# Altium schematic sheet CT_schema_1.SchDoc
size 736 x 683 mm
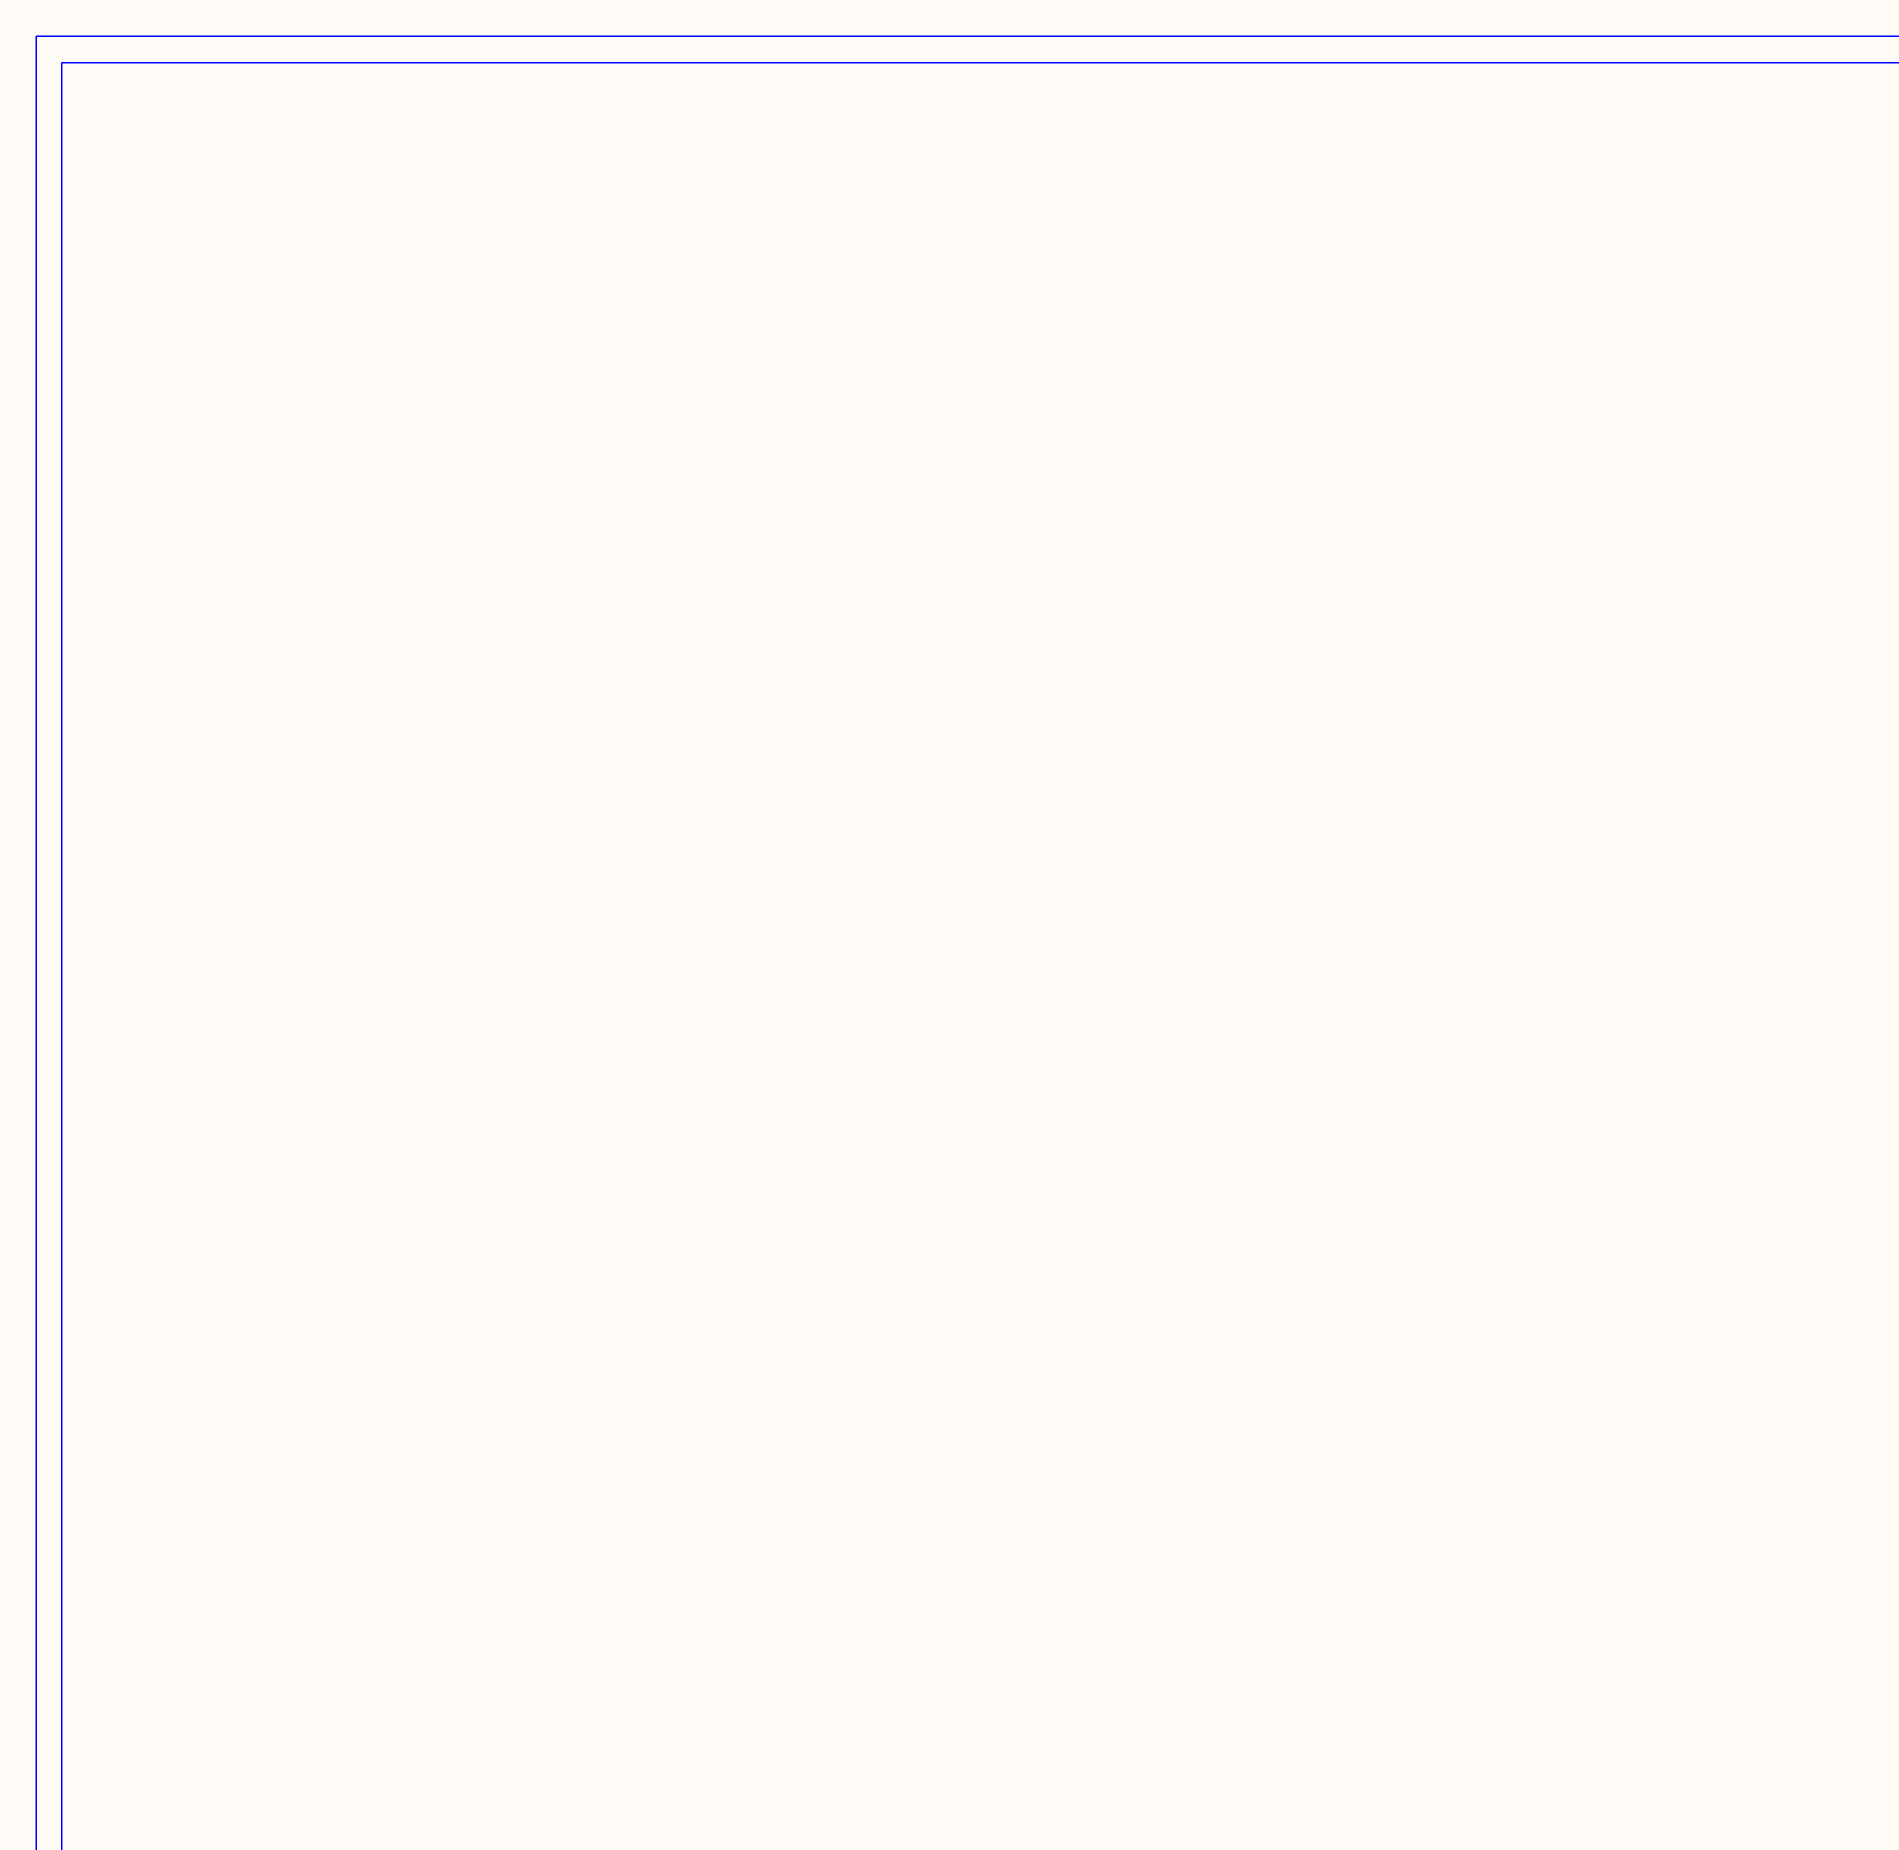
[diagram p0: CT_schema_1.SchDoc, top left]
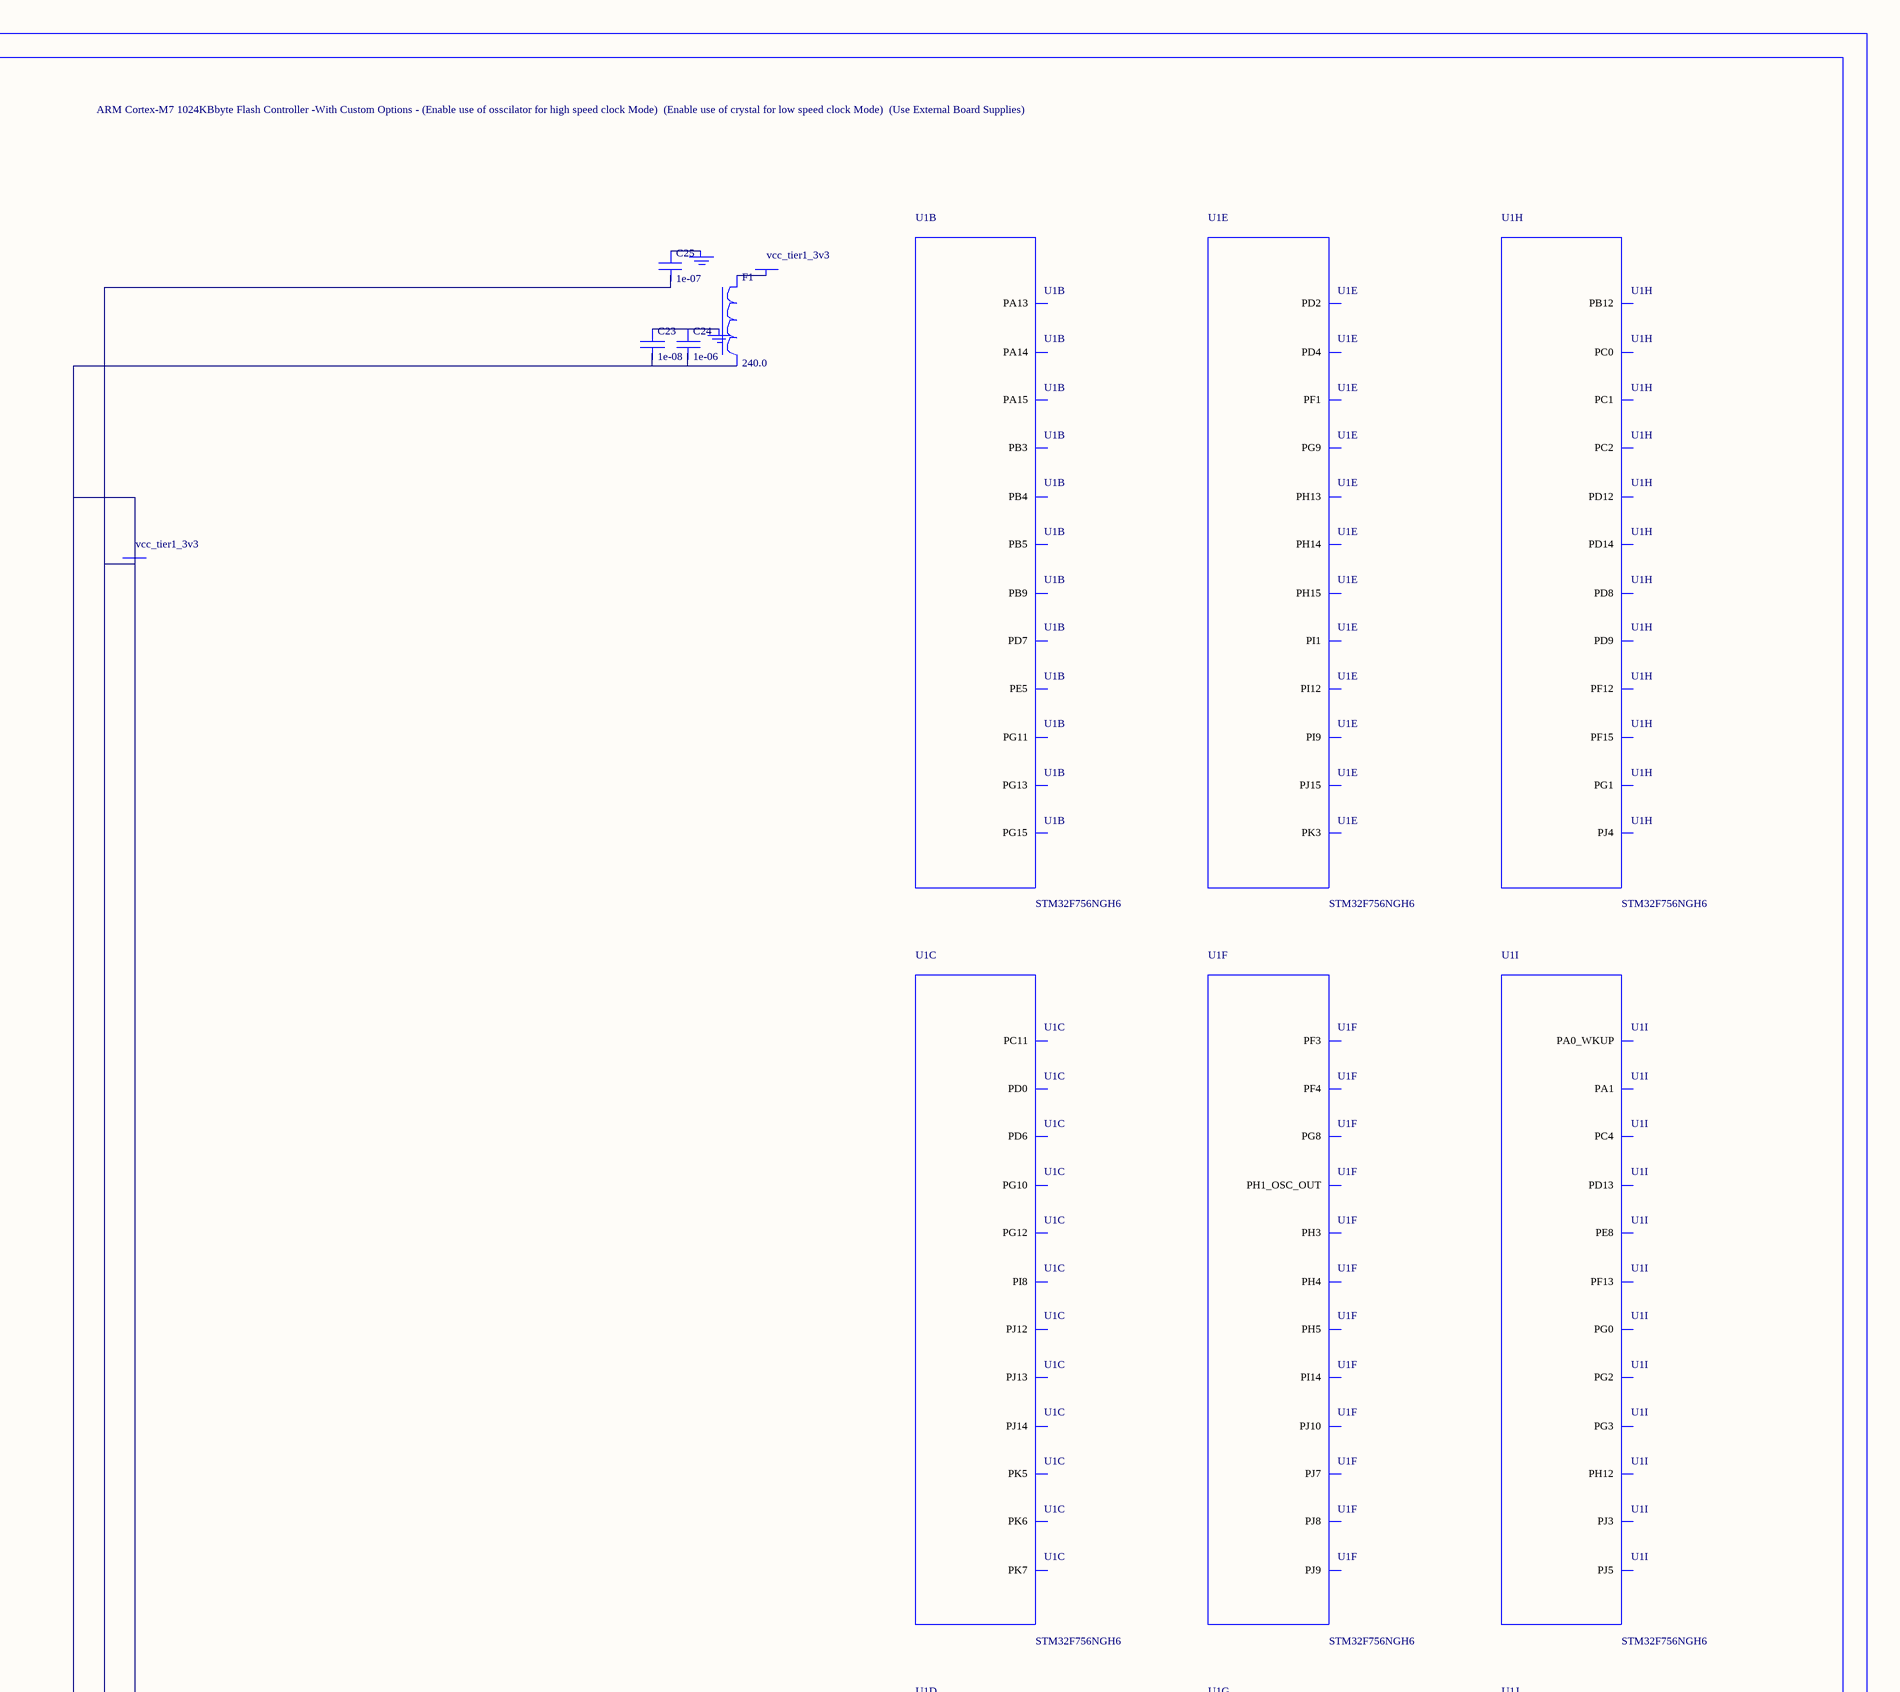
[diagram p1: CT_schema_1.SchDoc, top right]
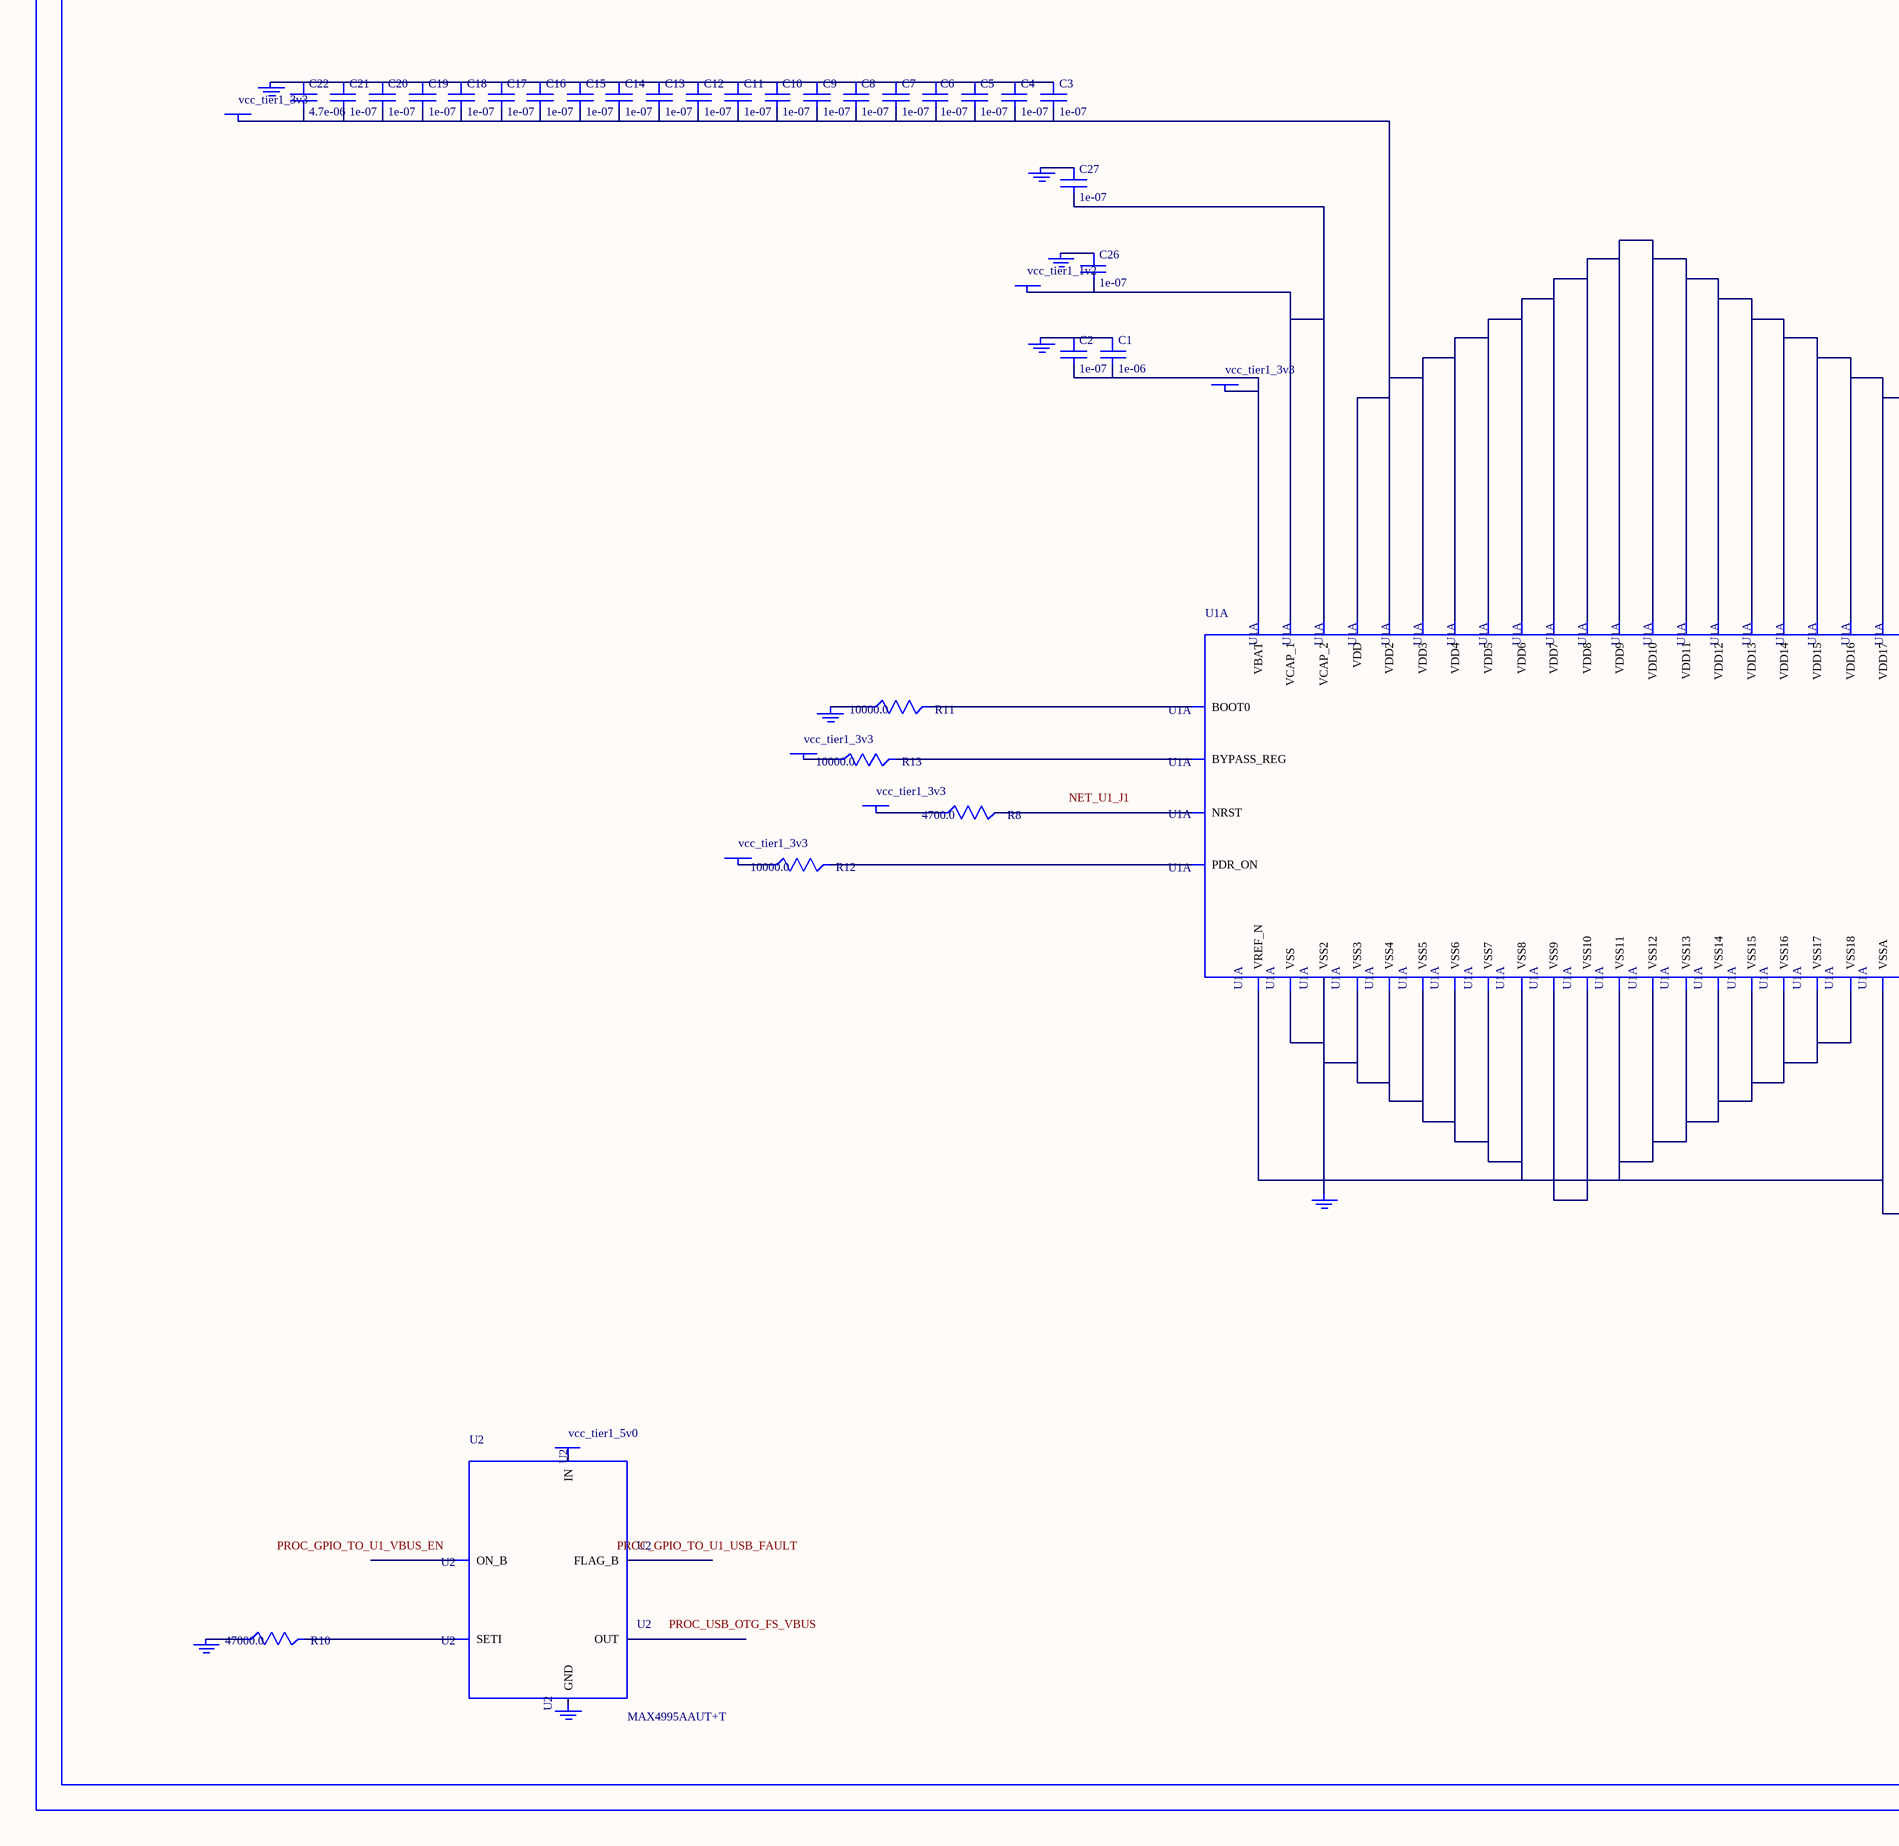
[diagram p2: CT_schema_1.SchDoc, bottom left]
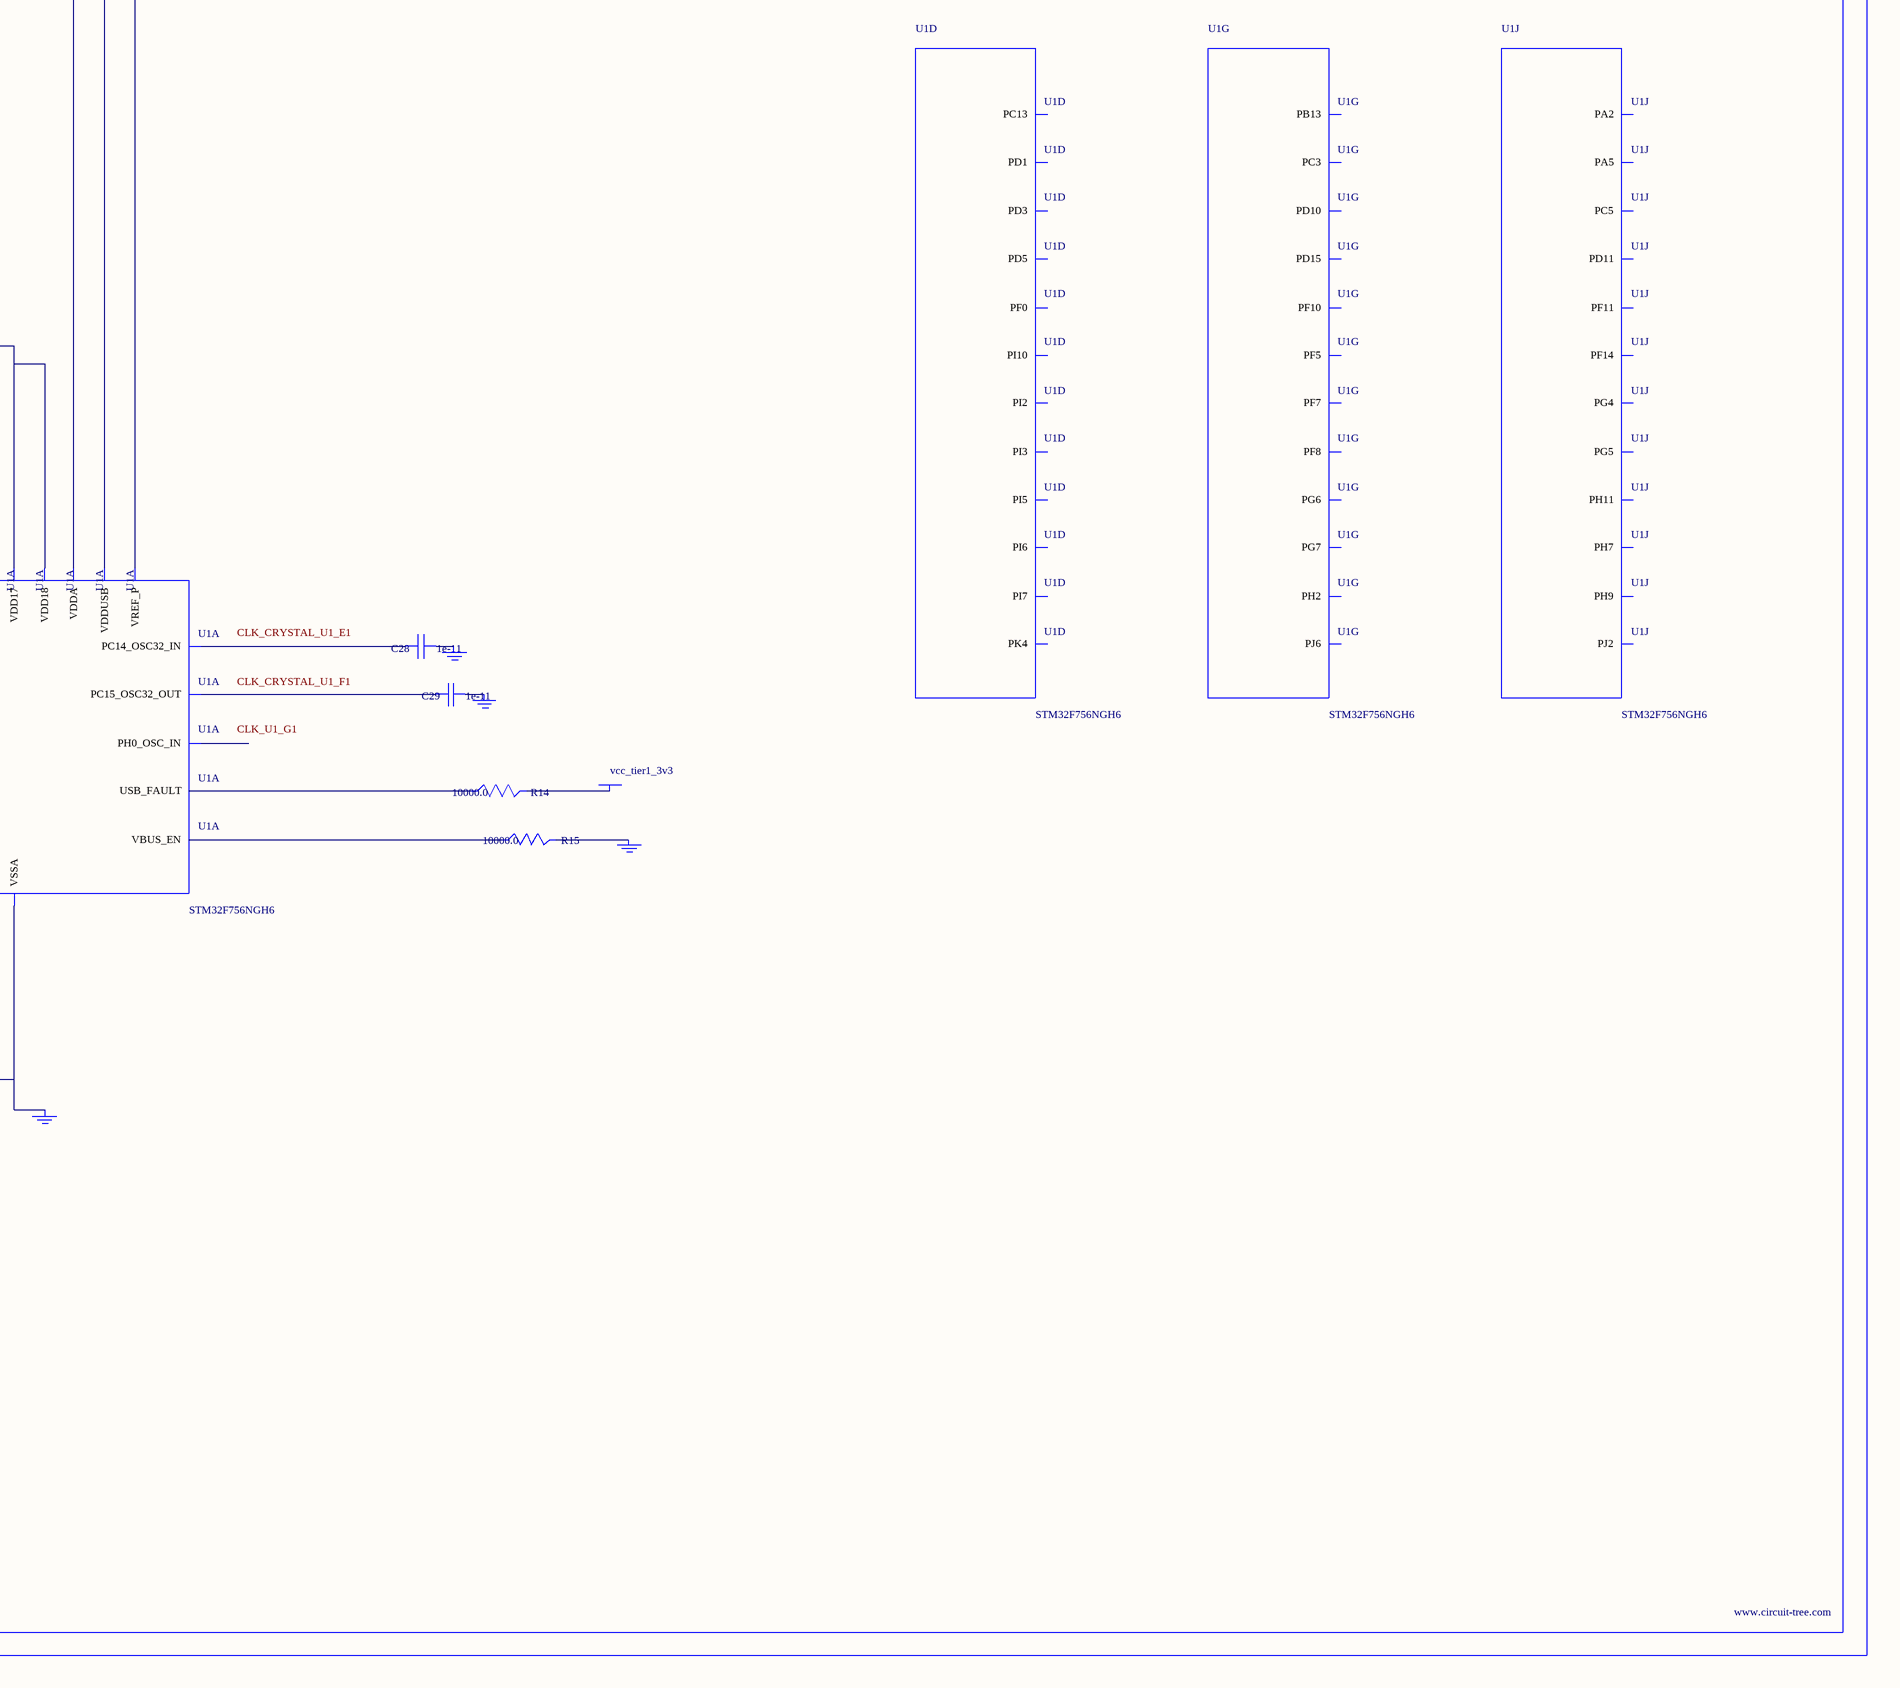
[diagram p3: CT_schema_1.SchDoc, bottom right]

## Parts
BORDER0  (no value)
C1  1e-06  [C0603]
C2  1e-07  [C0603]
C3  1e-07  [C0603]
C4  1e-07  [C0603]
C5  1e-07  [C0603]
C6  1e-07  [C0603]
C7  1e-07  [C0603]
C8  1e-07  [C0603]
C9  1e-07  [C0603]
C10  1e-07  [C0603]
C11  1e-07  [C0603]
C12  1e-07  [C0603]
C13  1e-07  [C0603]
C14  1e-07  [C0603]
C15  1e-07  [C0603]
C16  1e-07  [C0603]
C17  1e-07  [C0603]
C18  1e-07  [C0603]
C19  1e-07  [C0603]
C20  1e-07  [C0603]
C21  1e-07  [C0603]
C22  4.7e-06  [C0603]
C23  1e-08  [C0603]
C24  1e-06  [C0603]
C25  1e-07  [C0603]
C26  1e-07  [C0603]
C27  1e-07  [C0603]
C28  1e-11  [C0402]
C29  1e-11  [C0402]
F1  240.0  [L0603]
GND_INSTANCE_0_0  (no value)
GND_INSTANCE_0_1  (no value)
GND_INSTANCE_0_2  (no value)
GND_INSTANCE_0_3  (no value)
GND_INSTANCE_0_4  (no value)
GND_INSTANCE_0_5  (no value)
GND_INSTANCE_0_6  (no value)
GND_INSTANCE_0_7  (no value)
GND_INSTANCE_0_8  (no value)
GND_INSTANCE_0_9  (no value)
GND_INSTANCE_0_10  (no value)
GND_INSTANCE_0_11  (no value)
GND_INSTANCE_0_12  (no value)
GND_INSTANCE_0_13  (no value)
POWER_INSTANCE_0_0  vcc_tier1_3v3
POWER_INSTANCE_0_1  vcc_tier1_3v3
POWER_INSTANCE_0_2  vcc_tier1_3v3
POWER_INSTANCE_0_3  vcc_tier1_3v3
POWER_INSTANCE_0_4  vcc_tier1_3v3
POWER_INSTANCE_0_5  vcc_tier1_3v3
POWER_INSTANCE_0_6  vcc_tier1_1v2
POWER_INSTANCE_0_7  vcc_tier1_3v3
POWER_INSTANCE_0_8  vcc_tier1_3v3
POWER_INSTANCE_0_9  vcc_tier1_5v0
R8  4700.0  [R0603]
R10  47000.0  [R0603]
R11  10000.0  [R0603]
R12  10000.0  [R0603]
R13  10000.0  [R0603]
R14  10000.0  [R0603]
R15  10000.0  [R0603]
U1  STM32F756NGH6  [TFBGA216]  (parts A,B,C,D,E,F,G,H,I,J of 14)
U2  MAX4995AAUT+T  [SOT-23-6]

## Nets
NetC1_1: C1.1 C2.1 GND_INSTANCE_0_0.0(GND)
NetC1_2: C1.2 C2.2 POWER_INSTANCE_0_0.0(PWR) U1.C1(VBAT)
NetC3_1: C3.1 C4.1 C5.1 C6.1 C7.1 C8.1 C9.1 C10.1 C11.1 C12.1 C13.1 C14.1 C15.1 C16.1 C17.1 C18.1 C19.1 C20.1 C21.1 C22.1 GND_INSTANCE_0_2.0(GND)
NetC3_2: C3.2 C4.2 C5.2 C6.2 C7.2 C8.2 C9.2 C10.2 C11.2 C12.2 C13.2 C14.2 C15.2 C16.2 C17.2 C18.2 C19.2 C20.2 C21.2 C22.2 POWER_INSTANCE_0_2.0(PWR) U1.E7(VDD2) U1.E8(VDD3) U1.E9(VDD4) U1.E10(VDD) U1.F4(VDD6) U1.F5(VDD7) U1.F11(VDD5) U1.G5(VDD8) U1.H5(VDD10) U1.H11(VDD9) U1.J5(VDD12) U1.J11(VDD11) U1.K5(VDD14) U1.K11(VDD13) U1.L7(VDD16) U1.L8(VDD17) U1.L9(VDD18) U1.L10(VDD15)
NetC23_1: C23.1 C24.1 GND_INSTANCE_0_1.0(GND)
NetC23_2: C23.2 C24.2 C25.2 F1.2 POWER_INSTANCE_0_4.0(PWR) U1.G11(VDDUSB) U1.P1(VREF_P) U1.R1(VDDA)
NetC25_1: C25.1 GND_INSTANCE_0_4.0(GND)
NetC26_1: C26.1 GND_INSTANCE_0_5.0(GND)
NetC26_2: C26.2 C27.2 POWER_INSTANCE_0_6.0(PWR) U1.E11(VCAP_2) U1.L11(VCAP_1)
NetC27_1: C27.1 GND_INSTANCE_0_6.0(GND)
NetC28_1: C28.1 GND_INSTANCE_0_7.0(GND)
NetC28_2: C28.2 U1.E1(PC14_OSC32_IN)
NetC29_1: C29.1 GND_INSTANCE_0_8.0(GND)
NetC29_2: C29.2 U1.F1(PC15_OSC32_OUT)
NetF1_1: F1.1 POWER_INSTANCE_0_1.0(PWR)
NetGND_INSTANCE_0_3_0: GND_INSTANCE_0_3.0(GND) R11.1
NetGND_INSTANCE_0_9_0: GND_INSTANCE_0_9.0(GND) R15.2
NetGND_INSTANCE_0_10_0: GND_INSTANCE_0_10.0(GND) GND_INSTANCE_0_11.0(GND) U1.F2(VSS2) U1.F6(VSS3) U1.F7(VSS4) U1.F8(VSS5) U1.F9(VSS6) U1.F10(VSS) U1.G6(VSS8) U1.G10(VSS7) U1.H6(VSS10) U1.H10(VSS9) U1.J6(VSS12) U1.J10(VSS11) U1.K6(VSS14) U1.K7(VSS15) U1.K8(VSS16) U1.K9(VSS17) U1.K10(VSS13) U1.L6(VSS18) U1.M1(VSSA) U1.N1(VREF_N)
NetGND_INSTANCE_0_12_0: GND_INSTANCE_0_12.0(GND) R10.1
NetPOWER_INSTANCE_0_3_0: POWER_INSTANCE_0_3.0(PWR) R12.1
NetPOWER_INSTANCE_0_5_0: POWER_INSTANCE_0_5.0(PWR) R13.1
NetPOWER_INSTANCE_0_7_0: POWER_INSTANCE_0_7.0(PWR) R14.2
NetPOWER_INSTANCE_0_8_0: POWER_INSTANCE_0_8.0(PWR) R8.1
NetR8_2: R8.2 U1.J1(NRST)
NetR10_2: R10.2 U2.3(SETI)
NetR11_2: R11.2 U1.E6(BOOT0)
NetR12_2: R12.2 U1.E5(PDR_ON)
NetR13_2: R13.2 U1.L5(BYPASS_REG)
NetR14_1: R14.1 U1.A4(USB_FAULT)
NetR15_1: R15.1 U1.A2(VBUS_EN)

Not connected (* = marked no-connect by the designer): GND_INSTANCE_0_13 0(GND); POWER_INSTANCE_0_9 0(PWR); U1 A8(PB5) A9(PB4) A10(PB3) A11(PD7) A13(PA15) A14(PA14) A15(PA13) B1(PE5) B3(PG13) B4(PB9) B7(PG15) B8(PG11) B9(PJ13) B10(PJ12) B11(PD6) B12(PD0) B13(PC11) C2(PI8) C4(PK7) C5(PK6) C6(PK5) C7(PG12) C8(PG10) C9(PJ14) C10(PD5) C11(PD3) C12(PD1) C13(PI3) C14(PI2) D1(PC13) D2(PF0) D3(PI5) D4(PI7) D5(PI10) D6(PI6) D7(PK4) D8(PK3) D9(PG9) D10(PJ15) D11(PD4) D12(PD2) D13(PH15) D14(PI1) E2(PF1) E3(PI12) E4(PI9) E12(PH13) E13(PH14) G1(PH0_OSC_IN) H1(PH1_OSC_OUT) H2(PF3) H3(PI14) H4(PH4) H12(PJ8) H13(PJ10) H14(PG8) J2(PF4) J3(PH5) J4(PH3) J12(PJ7) J13(PJ9) J14(PG7) J15(PG6) K1(PF7) K3(PF5) K4(PH2) K12(PJ6) K13(PD15) K14(PB13) K15(PD10) L1(PF10) L3(PF8) L4(PC3) L12(PD14) L13(PB12) L14(PD9) L15(PD8) M2(PC0) M3(PC1) M4(PC2) M6(PF12) M7(PG1) M8(PF15) M9(PJ4) M10(PD12) M11(PD13) M12(PG3) M13(PG2) M14(PJ5) M15(PH12) N2(PA1) N3(PA0_WKUP) N5(PC4) N6(PF13) N7(PG0) N8(PJ3) N9(PE8) N10(PD11) N11(PG5) N12(PG4) N13(PH7) N14(PH9) N15(PH11) P2(PA2) P4(PA5) P5(PC5) P6(PF14) P7(PJ2) P8(PF11); U2 1(OUT) 2(GND) 4(ON_B) 5(IN) 6(FLAG_B)

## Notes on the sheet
- Labels drawn without touching a wire or pin: CLK_CRYSTAL_U1_E1, CLK_CRYSTAL_U1_F1, CLK_U1_G1, NET_U1_J1, PROC_GPIO_TO_U1_USB_FAULT, PROC_GPIO_TO_U1_VBUS_EN, PROC_USB_OTG_FS_VBUS

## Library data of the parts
BORDER0 = BORDER_PAGE0
C1 C24 = C0603C105K3RACTU
C2-C21 C25-C27 = 06035C104K4Z2A
C22 = GRM188R6YA475KE15D
C23 = 06035C103K4Z2A
C28 C29 = C0402C100K3GACTU
F1 = Z0603C241ASMST
GND_INSTANCE_0_0-GND_INSTANCE_0_13 = GND
POWER_INSTANCE_0_0-POWER_INSTANCE_0_9 = PWR
R8 = RC0603JR-074K7L
R10 = RC0603JR-0747KL
R11-R15 = RC0603JR-0710KL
